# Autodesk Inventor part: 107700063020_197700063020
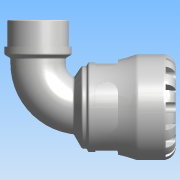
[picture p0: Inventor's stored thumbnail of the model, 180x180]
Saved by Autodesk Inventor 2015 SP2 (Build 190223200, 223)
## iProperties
Created: 2016-12
Part Number: 107700063020_197700063020
Material: PVC-Piping
Description: PLASSON 90° ELBOW WITH MALE INTEGRAL BRASS 63X2" SERIES 1
Document SubType Name: Modeling
Designer: KIM
Mass: 664.223 g
Surface Area: 733.008 cm^2
Volume: 474.445 cm^3
Density: 1.4 g/cm^3
Appearance: Smooth - White
Author: KIM
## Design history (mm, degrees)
derived "1077.ipt"
feature "Solid1::1077.ipt"
tag "TaggingFeature1"
body "Solid1"
other parameters: "d1" = 37.8, "d2" = 63, "d3" = 78.75, "d4" = 103, "d8" = 87.55, "d13" = 9.7, "d14" = 9.7, "d15" = 0, "d17" = 360 deg, "d19" = 8 deg, "d20" = 1.26, "d21" = 1.26, "d22" = 8 deg, "d24" = 0, "d26" = 360 deg, "d33" = 10.3, "d43" = 80.34, "d51" = 1.03, "d54" = 22.05, "d55" = 13.86, "d57" = 19.012, "d58" = 0, "d74" = 0, "d82" = 1.26, "d115" = 360 deg, "d207" = 90 deg, "d228" = 18.7425, "d247" = 2.06, "d248" = 5.4, "d268" = 48.1525, "d269" = 5.4, "d270" = 134, "d276" = 59.614, "d277" = 26, "d278" = 65.5754, "d279" = 85, "d280" = 33.8, "d281" = 8.9421, "d283" = 53.6526, "d286" = 0, "d287" = 0, "d288" = 41.7298, "d290" = 13.3437, "d292" = 30 deg, "d294" = 5.9614, "d296" = 30 deg, "d_" = 63, "E_" = 103, "A_" = 134, "A_1" = 85, "l_2" = 26, "R_" = 59.614, "d9" = 12.125, "d11" = 103, "d12" = 78.75, "d289" = 41.7298
